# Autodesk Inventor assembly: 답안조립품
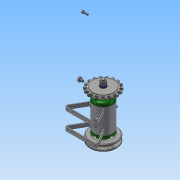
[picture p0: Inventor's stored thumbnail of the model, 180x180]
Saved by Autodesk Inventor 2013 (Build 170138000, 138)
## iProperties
Created: 2016-03
Part Number: 답안조립품
Document SubType Name: Assembly
Designer: Administrator
Author: Administrator
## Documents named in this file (16)
- C:\Users\Administrator\Desktop\460308V1025\답안조립품.iam
- C:\Users\Administrator\Desktop\460308V1025\본체.ipt
- C:\Users\Administrator\Desktop\460308V1025\V벨트풀리.ipt
- C:\Users\Administrator\Desktop\460308V1025\너트 M 8.ipt
- C:\Users\Administrator\Desktop\460308V1025\니플 M 6 x 0.75.ipt
- C:\Users\Administrator\Desktop\460308V1025\베어링 15 x 32 x 9.ipt
- C:\Users\Administrator\Desktop\460308V1025\볼트 M 6 x 8.ipt
- C:\Users\Administrator\Desktop\460308V1025\볼트 M4 x 12.ipt
- C:\Users\Administrator\Desktop\460308V1025\스프로킷.ipt
- C:\Users\Administrator\Desktop\460308V1025\스프링와셔 8.ipt
- C:\Users\Administrator\Desktop\460308V1025\오일 실 15 25 7.ipt
- C:\Users\Administrator\Desktop\460308V1025\와셔 6x11.5.ipt
- C:\Users\Administrator\Desktop\460308V1025\와셔 8x17.ipt
- C:\Users\Administrator\Desktop\460308V1025\축.ipt
- C:\Users\Administrator\Desktop\460308V1025\커버.ipt
- C:\Users\Administrator\Desktop\460308V1025\키 3 x 3 x 12.ipt
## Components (4 placed, 3 different names)
1. V벨트풀리:1
2. KS B 2023 6002 - 15 x 32 x 9:1
3. ISO 4762 M4 x 12:1
4. KS B 2023 6002 - 15 x 32 x 9:2
